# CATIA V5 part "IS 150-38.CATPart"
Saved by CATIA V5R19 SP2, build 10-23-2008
Part number: IS 150-38
Bounding box of the stored display mesh (mm): x -15.868 to 15.868, y -15.868 to 15.868, z 0 to 126
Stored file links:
  C:\Users\Bora\Desktop\3D Katı model\IS serisi\IS 150\IS 150-38.CATPart
  C:\Program Files\Dassault Systemes\B19\intel_a\reffiles\standard\MetricThickPitch.txt
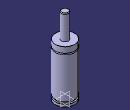
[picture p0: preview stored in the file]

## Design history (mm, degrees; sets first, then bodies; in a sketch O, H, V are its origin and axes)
Body1 (main body)
  Sketch1 on yz-plane, origin (0, 0, 0), H (0, 1, 0), V (0, 0, 1)
    point P3 (6, 125)
    point P5 (6, 125)
    point P7 (16, 76.5)
    point P8 (16, 74.5)
    point P12 (16, 74.5)
    point P13 (16, 76.5)
    line L1 (16, 0) -> (16, 4)
    line L2 (6, 125) -> (6, 86)
    arc A1 centre (5, 125) radius 1 from (6, 125) to (5, 126) ccw
    arc A2 centre (16, 75.5) radius 1 from (16, 76.5) to (16, 74.5) ccw
    line L3 (13.5, 7.5) -> (13.5, 4)
    line L4 (16, 7.5) -> (16, 74.5)
    line L5 (16, 76.5) -> (16, 86)
    line L6 (0, 0) -> (16, 0)
    line L7 (13.5, 4) -> (16, 4)
    line L8 (13.5, 7.5) -> (16, 7.5)
    line L9 (6, 86) -> (16, 86)
    line L10 (5, 126) -> (0, 126)
    horizontal: L6 H, L7 H, L8 H, L9 H
    tangency: L10 A1
    coincidence: P3 P5, P7 P13, P8 P12
  Shaft1: profile Sketch1, axis Sketch1.V, angle 360
  Sketch2 on face of Shaft1 from Sketch1.L6, origin (0, 0, 0), H (1, 0, 0), V (0, -1, 0)
    point P1 (0, 0)
  Hole1: placed by Sketch2, at (0, 0, 0) direction (0, 0, 1), diameter 6.647, depth 7, threaded "M8", thread diameter 8, thread depth 7, pitch 1.25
